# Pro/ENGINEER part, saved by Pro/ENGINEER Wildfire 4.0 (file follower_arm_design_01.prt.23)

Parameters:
  METRIC = "NO"

Other parameters: PITCH, DRILL_DIAMETER, THREAD_DIAMETER, THREADS_PER_INCH, THREAD_DEPTH, THREAD_LENGTH, DRILL_POINT_ANGLE, DRILL_DEPTH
